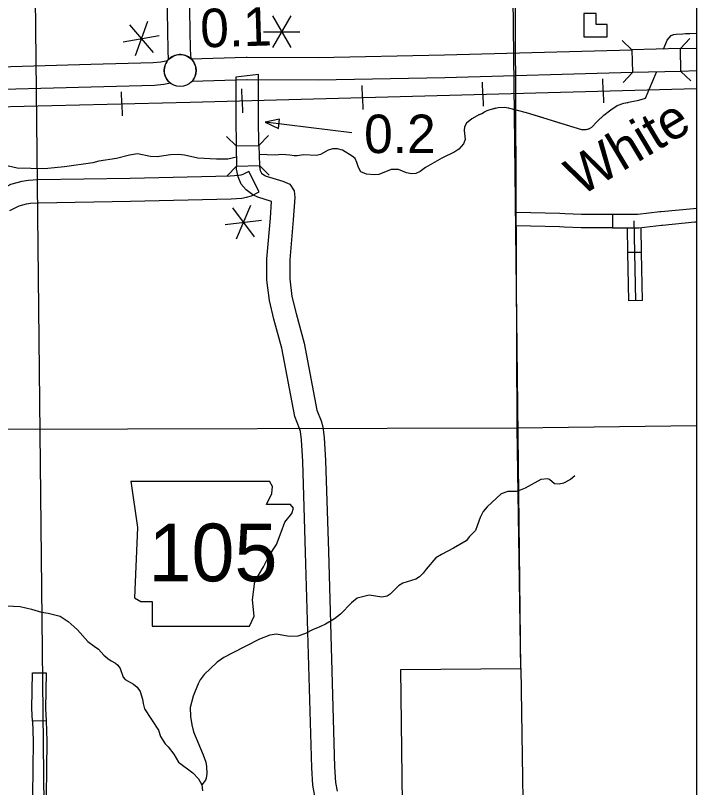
# Model space of a CAD drawing. Extents: x 1374139 to 1377472, y 1168351 to 1170484.
# Drawn here: x 1376448.1 to 1376597.4, y 1168905.5 to 1169074.9 of the extents above; entities that cross this region are included whole.
import ezdxf

# ---------------------------------------------------------------- set-up
doc = ezdxf.new("R2010")
doc.units = 0
doc.layers.add('26', color=7, linetype='Continuous')
doc.layers.add('Default', color=7, linetype='Continuous')

msp = doc.modelspace()

# ---------------------------------------------------------------- linework, layer by layer
at = {"layer": '26'}
msp.add_lwpolyline([(1375090, 1169579.43), (1376597.43, 1169579.43), (1376597.43, 1168653.79), (1375090, 1168653.79)], close=True, dxfattribs=at)
at = {"layer": 'Default'}
for p, q in [((1376558.91, 1168931.59), (1376555.31, 1169248.93)), ((1376450.62, 1169247.9), (1376454.96, 1168833.71)), ((1376508.46, 1169074.78), (1376504.46, 1169067.85)), ((1376504.46, 1169074.78), (1376508.46, 1169067.85)), ((1376473.09, 1169072.86), (1376478.24, 1169066.74)), ((1376477.03, 1169073.56), (1376474.3, 1169066.04)), ((1376471.72, 1169069.1), (1376479.6, 1169070.5)), ((1376502.46, 1169071.32), (1376510.46, 1169071.32)), ((1376583.26, 1169067.33), (1376583.4, 1169062.33)), ((1376593.87, 1169067.61), (1376597.43, 1169067.71)), ((1376594.01, 1169062.61), (1376593.87, 1169067.61)), ((1376597.43, 1169067.71), (1376597.43, 1169062.71)), ((1376498.65, 1169065.74), (1376498.91, 1169065.75)), ((1376501.39, 1169061.94), (1376496.39, 1169061.37)), ((1376597.43, 1169062.71), (1376594.01, 1169062.61)), ((1376550.57, 1169057.59), (1376550.5, 1169060.23)), ((1376576.96, 1169058.32), (1376576.89, 1169060.96)), ((1376497.79, 1169056.15), (1376497.72, 1169058.79)), ((1376524.18, 1169056.87), (1376524.11, 1169059.51)), ((1376471.4, 1169055.48), (1376471.34, 1169058.12)), ((1376524.18, 1169056.87), (1376524.25, 1169054.23)), ((1376550.57, 1169057.59), (1376550.64, 1169054.96)), ((1376576.96, 1169058.32), (1376577.03, 1169055.68)), ((1376471.4, 1169055.48), (1376471.46, 1169052.85)), ((1376497.79, 1169056.15), (1376497.86, 1169053.51)), ((1376496.47, 1169046.26), (1376501.47, 1169046.36)), ((1376496.56, 1169041.85), (1376501.56, 1169041.95)), ((1376501.52, 1169036.22), (1376499.23, 1169040.66)), ((1376499.64, 1169033.17), (1376496.47, 1169025.82)), ((1376495.67, 1169032.7), (1376500.44, 1169026.28)), ((1376568.51, 1169031.46), (1376568.51, 1169031.46)), ((1376579.01, 1169031.28), (1376579, 1169028.28)), ((1376494.08, 1169029.03), (1376502.03, 1169029.96)), ((1376585.37, 1169022.91), (1376582.37, 1169022.85)), ((1376585.58, 1169012.36), (1376582.58, 1169012.3)), ((1376186.66, 1168983.45), (1376558.09, 1168984.42)), ((1376473.33, 1168972.69), (1376474.86, 1168962.54)), ((1376504.46, 1168971.51), (1376503.76, 1168972.68)), ((1376504.29, 1168969.98), (1376504.46, 1168971.51)), ((1376503.11, 1168967.61), (1376504.29, 1168969.98)), ((1376508.35, 1168967.61), (1376503.11, 1168967.61)), ((1376509.03, 1168966.77), (1376508.35, 1168967.61)), ((1376507.17, 1168963.72), (1376508.69, 1168965.58)), ((1376508.69, 1168965.58), (1376509.03, 1168966.77)), ((1376506.32, 1168961.52), (1376507.17, 1168963.72)), ((1376474.86, 1168962.54), (1376474.18, 1168947.14)), ((1376505.31, 1168958.82), (1376506.32, 1168961.52)), ((1376503.62, 1168956.28), (1376505.31, 1168958.82)), ((1376502.43, 1168953.91), (1376503.62, 1168956.28)), ((1376500.57, 1168950.7), (1376502.43, 1168953.91)), ((1376500.07, 1168946.64), (1376500.57, 1168950.7)), ((1376474.18, 1168947.14), (1376475.53, 1168946.3)), ((1376500.4, 1168943.08), (1376500.07, 1168946.64)), ((1376475.53, 1168946.3), (1376478.07, 1168946.3)), ((1376478.07, 1168946.3), (1376478.07, 1168940.88)), ((1376499.39, 1168940.88), (1376500.4, 1168943.08)), ((1376478.07, 1168940.88), (1376499.39, 1168940.88)), ((1376451.78, 1168930.67), (1376454.78, 1168930.63)), ((1376454.77, 1168920.15), (1376451.77, 1168920.04))]:
    msp.add_line(p, q, dxfattribs=at)
for points in [[(1376480.58, 1169116.13), (1376481.02, 1169092.82), (1376481.46, 1169067.24), (1376481.56, 1169065.11)], [(1376486.56, 1169065.36), (1376486.45, 1169067.41), (1376486.02, 1169092.91), (1376485.58, 1169116.22)], [(1376454.23, 1168879.97), (1376454.26, 1168877.7), (1376533.25, 1168878.5), (1376532.58, 1168931.36), (1376558.91, 1168931.59), (1376558.09, 1168984.42), (1376557.63, 1169090.46)], [(1376590.19, 1169067.51), (1376591.01, 1169069.43), (1376591.84, 1169070.46), (1376592.47, 1169070.72), (1376592.97, 1169070.79), (1376597.43, 1169071.01)], [(1376590.19, 1169067.51), (1376591.01, 1169069.43), (1376591.84, 1169070.46), (1376592.35, 1169070.67)], [(1376594.97, 1169070.89), (1376597.43, 1169071.01)], [(1376581.08, 1169069.39), (1376583.26, 1169067.33)], [(1376593.87, 1169067.61), (1376595.94, 1169069.79)], [(1376417.51, 1169067.09), (1376426.65, 1169064.63), (1376431.4, 1169063.72), (1376434.23, 1169063.41), (1376436.99, 1169063.42), (1376464.56, 1169064.17), (1376478.25, 1169064.53), (1376479.91, 1169064.7), (1376481.44, 1169064.97)], [(1376498.91, 1169065.75), (1376514.45, 1169065.69), (1376542.13, 1169066.22), (1376583.26, 1169067.33)], [(1376593.87, 1169067.61), (1376583.26, 1169067.33)], [(1376486.55, 1169065.37), (1376498.65, 1169065.74)], [(1376482.07, 1169060), (1376480.59, 1169059.74), (1376478.57, 1169059.53), (1376464.69, 1169059.17), (1376437.06, 1169058.42), (1376433.97, 1169058.41), (1376430.66, 1169058.77), (1376425.53, 1169059.75), (1376416.66, 1169062.14)], [(1376583.4, 1169062.33), (1376542.25, 1169061.22), (1376514.48, 1169060.69), (1376498.89, 1169060.75)], [(1376501.47, 1169046.36), (1376501.36, 1169052.33), (1376501.39, 1169061.94)], [(1376549.82, 1169053.12), (1376550.04, 1169053.23), (1376550.31, 1169053.4), (1376550.89, 1169053.72), (1376551.5, 1169054.03), (1376552.13, 1169054.25), (1376553.94, 1169054.69), (1376555.37, 1169054.73), (1376556.14, 1169054.65), (1376560.04, 1169053.6), (1376572.19, 1169049.85), (1376573.19, 1169049.84), (1376573.98, 1169050.06), (1376574.45, 1169050.36), (1376575.59, 1169051.55), (1376577.09, 1169052.98), (1376578.62, 1169054.15), (1376580.01, 1169055.15), (1376581.47, 1169055.63), (1376583.24, 1169055.99), (1376584.77, 1169056.27), (1376586.2, 1169056.77), (1376588.61, 1169062.47)], [(1376583.4, 1169062.33), (1376581.33, 1169060.15)], [(1376594.01, 1169062.61), (1376583.4, 1169062.33)], [(1376585, 1169056.35), (1376586.2, 1169056.77), (1376588.61, 1169062.47)], [(1376596.18, 1169060.55), (1376594.01, 1169062.61)], [(1376498.8, 1169060.75), (1376486.71, 1169060.37)], [(1376496.39, 1169061.37), (1376496.36, 1169052.29), (1376496.47, 1169046.26)], [(1375980.44, 1169055.83), (1376021.26, 1169049.25), (1376024.29, 1169048.81), (1376032.84, 1169048.04), (1376042.84, 1169047.18), (1376068.56, 1169045.3), (1376103.8, 1169042.51), (1376110.96, 1169042.16), (1376115.25, 1169042.16), (1376124.29, 1169042.25), (1376144.46, 1169042.96), (1376209.36, 1169044.52), (1376253.07, 1169045.46), (1376293.61, 1169047.56), (1376378.04, 1169052.75), (1376397.45, 1169053.83), (1376425.66, 1169054.41), (1376486.36, 1169055.84), (1376597.43, 1169058.88)], [(1375980.44, 1169055.83), (1376021.26, 1169049.25), (1376024.29, 1169048.81), (1376032.84, 1169048.04), (1376042.84, 1169047.18), (1376068.56, 1169045.3), (1376103.8, 1169042.51), (1376110.96, 1169042.16), (1376115.25, 1169042.16), (1376124.29, 1169042.25), (1376144.46, 1169042.96), (1376209.36, 1169044.52), (1376253.07, 1169045.46), (1376293.61, 1169047.56), (1376378.04, 1169052.75), (1376397.45, 1169053.83), (1376425.66, 1169054.41), (1376486.36, 1169055.84), (1376597.43, 1169058.88)], [(1376575.81, 1169051.76), (1376577.09, 1169052.98), (1376578.62, 1169054.15), (1376580.01, 1169055.15), (1376581.47, 1169055.63), (1376582.42, 1169055.82)], [(1376549.82, 1169053.12), (1376550.04, 1169053.23), (1376550.31, 1169053.4), (1376550.89, 1169053.72), (1376551.5, 1169054.03), (1376552.13, 1169054.25), (1376553.48, 1169054.58)], [(1376556.1, 1169054.66), (1376556.14, 1169054.65), (1376560.04, 1169053.6), (1376563.71, 1169052.47)], [(1376549.82, 1169053.12), (1376548.11, 1169052.21), (1376546.94, 1169051.28), (1376546.52, 1169050.44), (1376546.49, 1169049.62), (1376546.7, 1169047.64), (1376546.31, 1169046.69), (1376545.26, 1169045.54), (1376544.44, 1169044.93), (1376541.58, 1169043.54), (1376537.99, 1169041.51), (1376536.79, 1169040.68), (1376535.84, 1169040.23), (1376534.95, 1169040.12), (1376533.82, 1169040.37), (1376532.06, 1169041.1), (1376530.46, 1169041.09), (1376527.73, 1169040.01), (1376526.76, 1169039.88), (1376525.07, 1169040.03), (1376523.78, 1169040.58), (1376523.29, 1169041.51), (1376522.96, 1169042.64), (1376522.54, 1169043.49), (1376521.92, 1169043.99), (1376519.81, 1169045.29), (1376518.7, 1169045.64), (1376517.62, 1169045.59), (1376516.65, 1169045.32), (1376514.95, 1169044.39), (1376514.06, 1169044.18), (1376511.22, 1169044.32), (1376509.83, 1169044.06), (1376509.18, 1169044.1), (1376508.24, 1169044.25), (1376506.46, 1169044.39), (1376505.02, 1169044.23), (1376503.28, 1169044.29), (1376501.54, 1169044.34)], [(1376566.23, 1169051.69), (1376572.19, 1169049.85), (1376573.19, 1169049.84), (1376573.85, 1169050.03)], [(1376521.8, 1169049.11), (1376502.81, 1169051.49)], [(1376496.47, 1169046.26), (1376494.31, 1169048.34)], [(1376503.55, 1169048.52), (1376501.47, 1169046.36)], [(1376496.47, 1169046.26), (1376496.56, 1169041.85)], [(1376501.47, 1169046.36), (1376501.56, 1169041.95)], [(1376496.52, 1169043.78), (1376494.66, 1169043.37), (1376492.18, 1169043.36), (1376488.05, 1169043.6), (1376485.13, 1169044.22), (1376483.85, 1169044.4), (1376482.03, 1169044.33), (1376479.14, 1169043.9), (1376477.67, 1169043.94), (1376474.82, 1169044.51), (1376473.08, 1169044.24), (1376470.23, 1169043.5), (1376466.37, 1169042.92), (1376465.06, 1169042.55), (1376458.81, 1169041.7), (1376454.46, 1169041.24), (1376448.43, 1169041.36), (1376441.07, 1169043.04), (1376440.66, 1169043.16)], [(1376494.48, 1169039.69), (1376496.56, 1169041.85)], [(1376513.73, 1168903.56), (1376513.29, 1168905.99), (1376513.05, 1168909.79), (1376511.7, 1168957.09), (1376511.05, 1168977), (1376510.79, 1168981.75), (1376510.55, 1168983.58), (1376510.34, 1168984.29), (1376509.31, 1168986.92), (1376506.47, 1169001.87), (1376504.76, 1169008.26), (1376503.76, 1169012.34), (1376503.22, 1169016.77), (1376503.2, 1169021.5), (1376503.97, 1169030.43), (1376504.24, 1169034.07), (1376501.19, 1169034.98), (1376500.11, 1169035.51), (1376498.64, 1169036.61), (1376497.54, 1169037.86), (1376496.87, 1169039.48), (1376496.57, 1169041.16), (1376496.56, 1169041.85)], [(1376501.56, 1169041.95), (1376503.72, 1169039.87)], [(1376501.56, 1169041.95), (1376501.56, 1169041.65), (1376501.7, 1169040.88), (1376501.84, 1169040.54), (1376502.05, 1169040.31), (1376502.74, 1169039.79), (1376503.03, 1169039.64), (1376506.68, 1169038.56), (1376508.23, 1169037.88), (1376509.15, 1169036.37), (1376509.32, 1169034.97), (1376508.95, 1169030.02), (1376508.2, 1169021.3), (1376508.22, 1169017.09), (1376508.69, 1169013.24), (1376509.6, 1169009.5), (1376511.35, 1169002.98), (1376514.14, 1168988.3), (1376515.07, 1168985.91), (1376515.45, 1168984.61), (1376515.77, 1168982.21), (1376516.05, 1168977.22), (1376516.7, 1168957.25), (1376518.05, 1168910.01), (1376518.26, 1168906.6), (1376518.6, 1168904.71)], [(1376499.23, 1169040.66), (1376497.9, 1169039.98), (1376497.46, 1169039.84), (1376497.04, 1169039.75), (1376495.14, 1169039.63), (1376473.21, 1169039.12), (1376452.88, 1169038.8), (1376450.89, 1169038.66), (1376449.44, 1169038.48), (1376447.01, 1169037.76), (1376444.69, 1169036.58), (1376443.47, 1169036.05), (1376442.56, 1169035.82), (1376441.1, 1169035.67), (1376429.24, 1169035.97), (1376425.41, 1169035.9), (1376410.29, 1169034.97), (1376388.27, 1169033.37), (1376364.42, 1169031.91), (1376353.21, 1169030.9), (1376349.89, 1169030.28), (1376346.55, 1169029.37), (1376343.06, 1169028.03), (1376340.93, 1169026.64)], [(1376446.83, 1169032.06), (1376448.86, 1169033.09), (1376450.48, 1169033.57), (1376451.38, 1169033.68), (1376453.09, 1169033.8), (1376473.31, 1169034.12), (1376495.36, 1169034.63), (1376497.72, 1169034.78), (1376498.72, 1169035), (1376499.8, 1169035.33), (1376501.52, 1169036.22)], [(1376557.9, 1169028.74), (1376557.88, 1169031.74), (1376567.48, 1169031.5), (1376568.51, 1169031.46)], [(1376568.51, 1169031.46), (1376572.21, 1169031.31), (1376579.01, 1169031.28)], [(1376579.01, 1169031.28), (1376581.48, 1169031.27), (1376584.56, 1169031.29), (1376589.36, 1169031.85)], [(1376589.36, 1169031.85), (1376589.66, 1169031.89), (1376596.79, 1169032.55), (1376597.43, 1169032.61)], [(1376584.08, 1169012.33), (1376583.73, 1169029.79)], [(1376589.71, 1169028.87), (1376589.97, 1169028.9), (1376597.05, 1169029.57), (1376597.43, 1169029.6)], [(1376568.39, 1169028.46), (1376567.38, 1169028.5), (1376557.9, 1169028.74)], [(1376579, 1169028.28), (1376572.15, 1169028.31), (1376568.39, 1169028.46)], [(1376579, 1169028.28), (1376581.48, 1169028.27), (1376584.74, 1169028.29), (1376589.71, 1169028.87)], [(1376582.37, 1169022.85), (1376582.26, 1169028.27)], [(1376585.37, 1169022.91), (1376585.26, 1169028.35)], [(1376582.58, 1169012.3), (1376582.37, 1169022.85)], [(1376585.58, 1169012.36), (1376585.37, 1169022.91)], [(1376558.09, 1168984.42), (1376597.43, 1168984.91)], [(1376570.71, 1168973.9), (1376569.79, 1168973.09), (1376568.23, 1168972.26), (1376567.32, 1168972.01), (1376566.3, 1168972.1), (1376565.19, 1168973.09), (1376564.81, 1168973.24), (1376563.27, 1168973.04), (1376559.81, 1168971.17), (1376558.74, 1168970.76), (1376557.85, 1168970.47), (1376556.05, 1168970.42), (1376554.55, 1168969.92), (1376551.49, 1168967.06), (1376550.66, 1168966.07), (1376549.94, 1168964.75), (1376549.35, 1168962.91), (1376548.93, 1168961.87), (1376547.6, 1168960.53), (1376546.87, 1168959.61), (1376544.14, 1168958.01), (1376541.46, 1168956.65), (1376540.22, 1168955.85), (1376538.1, 1168953.42), (1376537.46, 1168952.5), (1376536.67, 1168951.68), (1376535.84, 1168951.19), (1376532.99, 1168950.35), (1376532.1, 1168949.76), (1376530.24, 1168947.88), (1376529.59, 1168947.48), (1376528.4, 1168947.27), (1376525.61, 1168947.72), (1376523.03, 1168947.05), (1376521.78, 1168945.99), (1376519.33, 1168943.55), (1376518.06, 1168942.47), (1376516.04, 1168941.33), (1376514.78, 1168940.71), (1376513.17, 1168940.11), (1376511.64, 1168939.28), (1376510, 1168938.73), (1376508.12, 1168938.6), (1376505.31, 1168939.15), (1376503.87, 1168938.91), (1376501.56, 1168938.02), (1376495.57, 1168935), (1376493.76, 1168934.03), (1376492.33, 1168933.02), (1376489.45, 1168930.27), (1376488.59, 1168929.09), (1376488.13, 1168928.23), (1376487.03, 1168925.57), (1376486.4, 1168923.03), (1376486.44, 1168921.09), (1376486.73, 1168919.21), (1376487.12, 1168917.68), (1376489.26, 1168912.69), (1376489.79, 1168911.02), (1376489.97, 1168910.13), (1376490.06, 1168908.55), (1376489.89, 1168907.54), (1376489.76, 1168907.12), (1376488.91, 1168906.07)], [(1376473.33, 1168972.69), (1376503.76, 1168972.68)], [(1376446.16, 1168945.36), (1376449.06, 1168945.2), (1376451.6, 1168944.62), (1376453.77, 1168943.98), (1376455.22, 1168943.74), (1376457.88, 1168943.08), (1376459.63, 1168941.91), (1376460.94, 1168940.78), (1376461.66, 1168940.12), (1376463.97, 1168937.52), (1376465.32, 1168936.48)], [(1376465.32, 1168936.48), (1376466.26, 1168935.81), (1376467.44, 1168934.56), (1376468.3, 1168933.8), (1376469.06, 1168933.26), (1376470.01, 1168932.77), (1376470.52, 1168932.36), (1376471.06, 1168931.62), (1376471.72, 1168929.71), (1376472.15, 1168929.17), (1376473.94, 1168928.16), (1376474.76, 1168927.48), (1376475.41, 1168926.54), (1376475.95, 1168924.89), (1376476.08, 1168923.91), (1376476.38, 1168922.74), (1376479.41, 1168918.1), (1376479.89, 1168916.65), (1376480.86, 1168915.07), (1376481.53, 1168914.43), (1376482.82, 1168912.78), (1376483.81, 1168911.03), (1376486.94, 1168908.72), (1376488.23, 1168907.43), (1376488.91, 1168906.07), (1376489.07, 1168904.73)], [(1376558.91, 1168931.59), (1376559.73, 1168878.77)], [(1376451.77, 1168920.04), (1376451.67, 1168922.82), (1376451.78, 1168930.67)], [(1376454.78, 1168930.63), (1376454.67, 1168922.85), (1376454.77, 1168920.15)], [(1376451.77, 1168920.04), (1376451.93, 1168915.72), (1376451.86, 1168909.56)], [(1376454.77, 1168920.15), (1376454.93, 1168915.76), (1376454.86, 1168909.52)], [(1376451.86, 1168909.56), (1376451.79, 1168903.78), (1376451.53, 1168899.07)], [(1376454.86, 1168909.52), (1376454.79, 1168903.68), (1376454.52, 1168898.9)]]:
    msp.add_lwpolyline(points, dxfattribs=at)
for points in [[(1376572.71, 1169070.22), (1376577.79, 1169070.22), (1376577.79, 1169072.9), (1376575.39, 1169072.9), (1376575.39, 1169075.3), (1376572.71, 1169075.3)], [(1376505.72, 1169050.1), (1376505.97, 1169052.12), (1376502.81, 1169051.49)]]:
    msp.add_lwpolyline(points, close=True, dxfattribs=at)
msp.add_circle((1376484.18, 1169062.79), 3.5, dxfattribs=at)
for start, end in [(47.2649, 138.4345), (316.3383, 47.5081), (141.5906, 232.8921)]:
    msp.add_arc((1376484.18, 1169062.79), 3.5, start, end, dxfattribs=at)

# ---------------------------------------------------------------- texts
for s, rotation, p in [('0.1', 1.7635, (1376488.71, 1169067.84)), ('White', 30.8146, (1376571.96, 1169035.11))]:
    msp.add_text(s, height=8.448, rotation=rotation, dxfattribs=at).set_placement(p)
for s, height, p in [('0.2', 8.448, (1376524.52, 1169044.68)), ('105', 12.672, (1376477.24, 1168950.72))]:
    msp.add_text(s, height=height, dxfattribs=at).set_placement(p)

doc.saveas('drawing.dxf')
